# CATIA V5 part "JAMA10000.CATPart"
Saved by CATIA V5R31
Part number: JAMA10000
Revision: 1
Nomenclature: COUNTERSHAFT
Source: Unknown
Property "部品番号(A社)": "JAMA10000"
Property "部品名称(A社)": "COUNTERSHAFT"
Property "Version(A社)": "1"
Property "材質(A社)": "SNCM220"
Bounding box of the stored display mesh (mm): x -32.85 to 32.85, y -95.3 to 0, z -32.85 to 32.85
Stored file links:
  \\solize.local\damia\dept\DDE_Design\10_order\2305701_JAMA_変換検証STEP3_お手本モデル作成\Fini\06_ホンダ\CATIAV5\JAMA10000.CATPart
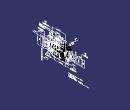
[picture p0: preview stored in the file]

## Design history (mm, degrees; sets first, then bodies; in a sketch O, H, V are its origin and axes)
f4a2d38f3ddc11d3a929006094b99c4b_11 "CATTPSSet"
TTRSSet1
Set1 "SECT"
  DatumSurface1 "Fill.3"
  DatumSurface2 "Fill.2"
Set2 "Geometrical Set for VIEW"
  Set3 "FRONT"
    DatumCurve1 "DETAIL AREA c"
    DatumCurve2 "DETAIL AREA a"
    DatumCurve3 "DETAIL AREA d"
    Line1: stored without definition
    Circle1 "DETAIL AREA e": stored without definition
    DatumCurve4
    Circle2: stored without definition
  Set4 "DETAIL AREA a"
    DatumSurface3
    Intersect1: ToIntersect1 yz-plane, ToIntersect2 DatumSurface3
  Set5 "DETAIL AREA c"
    Circle3 "DETAIL AREA g": stored without definition
    DatumCurve5 "DETAIL AREA f"
    Circle4 to Circle11: stored without definition
    Line2: stored without definition
    DatumCurve6
    DatumCurve7
    Circle12: stored without definition
    Circle13: stored without definition
    Line3: stored without definition
  Set6 "DETAIL AREA e"
    Circle14: stored without definition
    DatumCurve8
    DatumCurve9
  Set7 "DETAIL AREA f"
    Circle15 to Circle17: stored without definition
    Line4: stored without definition
    DatumCurve10
    Line5: stored without definition
    Line6: stored without definition
    Intersect2: ToIntersect1 yz-plane, ToIntersect2 Circle14
  Set8 "DETAIL AREA h"
    Circle18 "DETAIL AREA j": stored without definition
  Set9 "DETAIL AREA g This shape also allowed"
    DatumSurface4 "another"
    DatumSurface5 "Fill.1"
Body1 "FINAL" (main body)
  Solid1: solid without history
